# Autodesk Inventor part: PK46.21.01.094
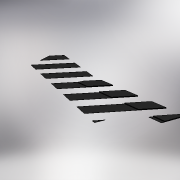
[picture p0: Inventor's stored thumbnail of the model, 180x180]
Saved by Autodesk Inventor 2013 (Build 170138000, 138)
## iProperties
Created: 2012-02
Part Number: PK46.21.01.094
Material: Aluminum-6061
Document SubType Name: Modeling
Designer: tedescj
Density: 2.71 g/cm^3
Mass: 1247.09 g
Surface Area: 3414.78 cm^2
Volume: 460.181 cm^3
Author: tedescj
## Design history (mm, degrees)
sketch "Sketch1"
  geometry: L1 (105.184, -95.669)-(560.563, -166.165); L2 (26.04, -191.675)-(45.636, -388); L3 (26.04, -191.675)-(105.184, -95.669) reference; L4 (185.636, -108.123)-(35.838, -289.838); L5 (266.087, -120.578)-(45.636, -388); L6 (45.636, -388)-(495.113, -388); L7 (346.539, -133.032)-(126.088, -400.455); L8 (426.99, -145.487)-(206.539, -412.909); L9 (507.442, -157.942)-(286.991, -425.364); L10 (367.443, -437.818)-(594.631, -162.223); L11 (447.894, -450.273)-(694.915, -150.62); L12 (528.346, -462.727)-(795.198, -139.017); L13 (608.797, -475.182)-(895.482, -127.414); L14 (689.249, -487.636)-(995.766, -115.81); L15 (769.7, -500.091)-(1096.049, -104.207); L16 (870.71, -515.728)-(899.043, -453.237) reference; L17 (1014.346, -537.964)-(960.99, -655.645) reference; L18 (1149.652, -239.537)-(1217.375, -90.169); L19 (1066.993, -249.502)-(1149.652, -239.537) reference; L20 (850.152, -512.546)-(899.043, -453.237); L21 (1066.993, -249.502)-(1196.333, -92.604); L22 (850.152, -512.546)-(870.71, -515.728); 1 further point; 1 other entity
  constraints: 44 end point, 13 parallel, 6 point on line, 1 collinear, 1 horizontal, 1 midpoint, 33 other
  dimensions: "d1" = 70 distance between parallel lines of L4 L3; "d2" = 70 distance between parallel lines of L5 L4 (= d1); "d3" = 1.53589 dimension on L6; "d4" = 388 vertical distance of L2.end point (0, 0); "d5" = 104.5 deg dimension on L2; "d6" = 298 dimension on L1; "d7" = 28.72812 dimension on L1; "d8" = 70 distance between parallel lines of L7 L5 (= d1); "d9" = 70 distance between parallel lines of L8 L7 (= d2); "d10" = 70 distance between parallel lines of L9 L8 (= d1); "d11" = 70 distance between parallel lines of L10 L9 (= d2); "d12" = 70 distance between parallel lines of L11 L10 (= d1); "d13" = 70 distance between parallel lines of L12 L11 (= d2); "d14" = 70 distance between parallel lines of L13 L12 (= d1); "d15" = 70 distance between parallel lines of L14 L13 (= d2); "d16" = 70 distance between parallel lines of L15 L14 (= d1)
feature "Surface1"
feature "Surface2"
feature "Trim1"
feature "Stitch Surface1"
feature "OffsetSrf1" dims "d18" = 1, "d19" = 1
feature "OffsetSrf2" dims "d20" = 1 (= d18), "d21" = 1
feature "OffsetSrf3" dims "d22" = 1 (= d18), "d23" = 1
feature "OffsetSrf4" dims "d24" = 1 (= d18), "d25" = 1
feature "Trim2"
feature "Trim10"
feature "Extend7" dims "d32" = 5
feature "Extend8" dims "d33" = 7.25
feature "Trim11"
feature "Trim12"
feature "Extend9" dims "d34" = 5
feature "Extend10" dims "d35" = 5
feature "Extend11" dims "d36" = 5
feature "Extend12" dims "d37" = 5
feature "Trim13"
feature "Trim14"
feature "Trim15"
feature "Trim16"
feature "Stitch Surface2"
feature "Trim17"
feature "Stitch Surface3"
extrude "Extrusion1" new body sketch "Sketch1" stored distance "d38" = 10; taper "d39" = 0 deg
split "Split1"
body "Solid1"
body "Srf3"
body "Srf4"
body "Srf5"
body "Srf6"
body "Srf7"
body "Srf8"
body "Srf9"
body "Srf1"
body "Srf2"
